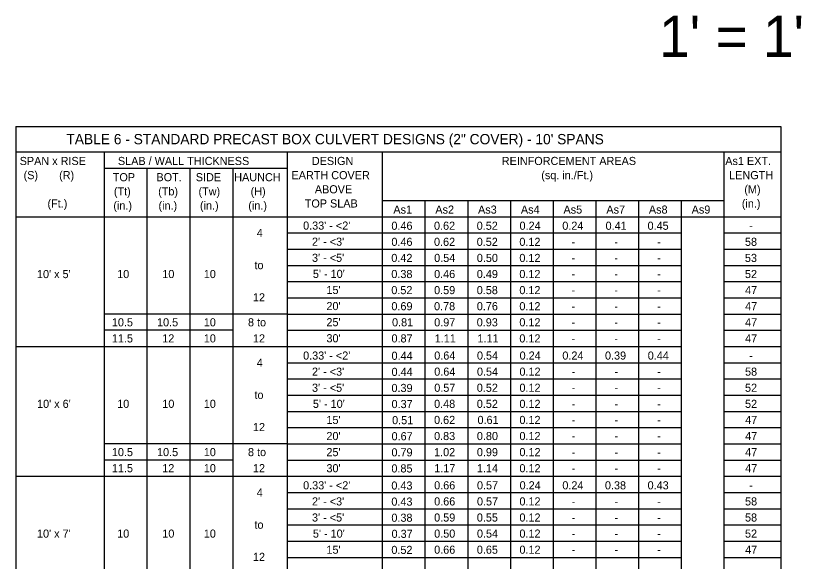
# Model space of a CAD drawing. Extents: x 10346.98 to 10349.19, y 76399.48 to 76400.59.
# Drawn here: x 10347.625 to 10348.236, y 76400.162 to 76400.586 of the extents above; entities that cross this region are included whole.
import ezdxf

# ---------------------------------------------------------------- set-up
doc = ezdxf.new("R2010")
doc.units = 0
doc.layers.add('AdhocPoint_dp', color=7, linetype='Continuous')
doc.layers.add('PlotBorder_dp', color=7, linetype='Continuous')

msp = doc.modelspace()

# ---------------------------------------------------------------- linework, layer by layer
at = {"layer": 'PlotBorder_dp'}
for p, q in [((10347.62504, 76400.49971), (10347.62504, 76399.82469)), ((10347.62504, 76400.49971), (10348.21977, 76400.49971)), ((10348.21977, 76400.49971), (10348.21977, 76399.82469)), ((10347.62504, 76400.47984), (10348.21977, 76400.47984)), ((10347.69367, 76400.47984), (10347.69367, 76399.82469)), ((10347.83612, 76400.47984), (10347.83612, 76399.82469)), ((10347.91, 76400.47984), (10347.91, 76399.82469)), ((10348.17559, 76400.47984), (10348.17559, 76399.82469)), ((10347.69367, 76400.46724), (10347.83612, 76400.46724)), ((10347.72703, 76400.46724), (10347.72703, 76399.82469)), ((10347.76039, 76400.46724), (10347.76039, 76399.82469)), ((10347.79375, 76400.46724), (10347.79375, 76399.82469)), ((10347.91, 76400.44209), (10348.17559, 76400.44209)), ((10347.9432, 76400.44209), (10347.9432, 76399.82469)), ((10347.97639, 76400.44209), (10347.97639, 76399.82469)), ((10348.00959, 76400.44209), (10348.00959, 76399.82469)), ((10348.04279, 76400.44209), (10348.04279, 76399.82469)), ((10348.07599, 76400.44209), (10348.07599, 76399.82469)), ((10348.07599, 76400.44209), (10348.07599, 76399.82469)), ((10348.10919, 76400.44209), (10348.10919, 76399.82469)), ((10348.14239, 76400.44209), (10348.14239, 76399.82469)), ((10347.62504, 76400.42949), (10348.21977, 76400.42949)), ((10347.83612, 76400.41689), (10348.14239, 76400.41689)), ((10348.17559, 76400.41689), (10348.21977, 76400.41689)), ((10347.83612, 76400.40429), (10348.14239, 76400.40429)), ((10348.17559, 76400.40429), (10348.21977, 76400.40429)), ((10347.83612, 76400.39169), (10348.14239, 76400.39169)), ((10348.17559, 76400.39169), (10348.21977, 76400.39169)), ((10347.83612, 76400.37909), (10348.14239, 76400.37909)), ((10348.17559, 76400.37909), (10348.21977, 76400.37909)), ((10347.83612, 76400.36649), (10348.14239, 76400.36649)), ((10348.17559, 76400.36649), (10348.21977, 76400.36649)), ((10347.83612, 76400.35389), (10347.69367, 76400.35389)), ((10347.83612, 76400.35389), (10348.14239, 76400.35389)), ((10348.17559, 76400.35389), (10348.21977, 76400.35389)), ((10347.79375, 76400.34129), (10347.69367, 76400.34129)), ((10347.83612, 76400.34129), (10348.14239, 76400.34129)), ((10348.17559, 76400.34129), (10348.21977, 76400.34129)), ((10347.62504, 76400.32869), (10348.14239, 76400.32869)), ((10347.83673, 76400.32869), (10347.9089, 76400.32869)), ((10348.17559, 76400.32869), (10348.21977, 76400.32869)), ((10347.83612, 76400.31609), (10348.14239, 76400.31609)), ((10348.17559, 76400.31609), (10348.21977, 76400.31609)), ((10347.83612, 76400.30349), (10348.14239, 76400.30349)), ((10348.17559, 76400.30349), (10348.21977, 76400.30349)), ((10347.83612, 76400.29089), (10348.14239, 76400.29089)), ((10348.17559, 76400.29089), (10348.21977, 76400.29089)), ((10347.83612, 76400.27829), (10348.14239, 76400.27829)), ((10348.17559, 76400.27829), (10348.21977, 76400.27829)), ((10347.83612, 76400.26569), (10348.14239, 76400.26569)), ((10348.17559, 76400.26569), (10348.21977, 76400.26569)), ((10347.83612, 76400.25309), (10347.69367, 76400.25309)), ((10347.83612, 76400.25309), (10348.14239, 76400.25309)), ((10348.17559, 76400.25309), (10348.21977, 76400.25309)), ((10347.79375, 76400.24049), (10347.69367, 76400.24049)), ((10347.83612, 76400.24049), (10348.14239, 76400.24049)), ((10347.83673, 76400.24049), (10347.9089, 76400.24049)), ((10348.17559, 76400.24049), (10348.21977, 76400.24049)), ((10347.62504, 76400.22789), (10348.14239, 76400.22789)), ((10348.17559, 76400.22789), (10348.21977, 76400.22789)), ((10347.83612, 76400.21529), (10348.14239, 76400.21529)), ((10348.17559, 76400.21529), (10348.21977, 76400.21529)), ((10347.83612, 76400.20269), (10348.14239, 76400.20269)), ((10348.17559, 76400.20269), (10348.21977, 76400.20269)), ((10347.83612, 76400.19009), (10348.14239, 76400.19009)), ((10348.17559, 76400.19009), (10348.21977, 76400.19009)), ((10347.83612, 76400.17749), (10348.14239, 76400.17749)), ((10348.17559, 76400.17749), (10348.21977, 76400.17749)), ((10347.83612, 76400.16489), (10348.14239, 76400.16489)), ((10348.17559, 76400.16489), (10348.21977, 76400.16489))]:
    msp.add_line(p, q, dxfattribs=at)

# ---------------------------------------------------------------- texts
at = {"layer": 'AdhocPoint_dp'}
for s, height, p in [("1' = 1'", 0.032, (10348.12518, 76400.55363)), ('TABLE 6 - STANDARD PRECAST BOX CULVERT DESIGNS (2" COVER) - 10\' SPANS', 0.008, (10347.66442, 76400.48578)), ('SLAB / WALL THICKNESS', 0.0063, (10347.70449, 76400.46968)), ('As1', 0.0063, (10347.91862, 76400.43192)), ('As2', 0.0063, (10347.95125, 76400.43192)), ('As3', 0.0063, (10347.98444, 76400.43192)), ('As4', 0.0063, (10348.01777, 76400.43192)), ('As5', 0.0063, (10348.05087, 76400.43192)), ('As7', 0.0063, (10348.08421, 76400.43192)), ('As8', 0.0063, (10348.11726, 76400.43192)), ('As9', 0.0063, (10348.15051, 76400.43192)), ("10' x 5'", 0.0063, (10347.64157, 76400.38182))]:
    msp.add_text(s, height=height, dxfattribs=at).set_placement(p)
at = {"layer": 'PlotBorder_dp'}
for s, p in [('SPAN x RISE', (10347.62812, 76400.46968)), ('DESIGN', (10347.85522, 76400.46968)), ('REINFORCEMENT AREAS', (10348.0029, 76400.46968)), ('(S)       (R)', (10347.63117, 76400.45868)), ('EARTH COVER', (10347.83943, 76400.45868)), ('(sq. in./Ft.)', (10348.03359, 76400.45868)), ('TOP', (10347.7005, 76400.45708)), ('BOT.', (10347.73443, 76400.45708)), ('SIDE', (10347.76502, 76400.45708)), ('HAUNCH', (10347.79491, 76400.45708)), ('(Tt)', (10347.70134, 76400.44608)), ('(Tb)', (10347.73577, 76400.44608)), ('(Tw)', (10347.76713, 76400.44608)), ('(H)', (10347.80766, 76400.44608)), ('ABOVE', (10347.85757, 76400.44768)), ('(Ft.)', (10347.64974, 76400.43668)), ('(in.)', (10347.70095, 76400.43508)), ('(in.)', (10347.73604, 76400.43508)), ('(in.)', (10347.76828, 76400.43508)), ('(in.)', (10347.80585, 76400.43508)), ('TOP SLAB', (10347.84974, 76400.43668)), ("0.33' - <2'", (10347.84847, 76400.41948)), ('0.46', (10347.91709, 76400.41937)), ('0.62', (10347.95022, 76400.41937)), ('0.52', (10347.98342, 76400.41937)), ('0.24', (10348.0167, 76400.41937)), ('0.24', (10348.04993, 76400.41937)), ('0.41', (10348.08359, 76400.41937)), ('0.45', (10348.11623, 76400.41937)), ('4', (10347.81242, 76400.41377)), ("2' - <3'", (10347.85537, 76400.40698)), ('0.46', (10347.91709, 76400.40687)), ('0.62', (10347.95022, 76400.40687)), ('0.52', (10347.98342, 76400.40687)), ('0.12', (10348.01658, 76400.40687)), ('-', (10348.05721, 76400.40687)), ('-', (10348.09042, 76400.40687)), ('-', (10348.1236, 76400.40687)), ("3' - <5'", (10347.85537, 76400.39448)), ('0.42', (10347.91702, 76400.39437)), ('0.54', (10347.95034, 76400.39437)), ('0.50', (10347.9835, 76400.39437)), ('0.12', (10348.01658, 76400.39437)), ('-', (10348.05721, 76400.39437)), ('-', (10348.09042, 76400.39437)), ('-', (10348.1236, 76400.39437)), ('to', (10347.81064, 76400.38877)), ('10', (10347.70392, 76400.38187)), ('10', (10347.73901, 76400.38187)), ('10', (10347.77125, 76400.38187)), ("5' - 10'", (10347.85608, 76400.38198)), ('0.38', (10347.91704, 76400.38187)), ('0.46', (10347.95029, 76400.38187)), ('0.49', (10347.98349, 76400.38187)), ('0.12', (10348.01658, 76400.38187)), ('-', (10348.05721, 76400.38187)), ('-', (10348.09042, 76400.38187)), ('-', (10348.1236, 76400.38187)), ("15'", (10347.8666, 76400.36948)), ('0.52', (10347.91702, 76400.36937)), ('0.59', (10347.95029, 76400.36937)), ('0.58', (10347.98344, 76400.36937)), ('0.12', (10348.01658, 76400.36937)), ('12', (10347.80947, 76400.36377)), ('-', (10348.05721, 76400.36937)), ('-', (10348.09042, 76400.36937)), ('-', (10348.1236, 76400.36937)), ("20'", (10347.8666, 76400.35698)), ('0.69', (10347.91709, 76400.35687)), ('0.78', (10347.95024, 76400.35687)), ('0.76', (10347.98349, 76400.35687)), ('0.12', (10348.01658, 76400.35687)), ('-', (10348.05721, 76400.35687)), ('-', (10348.09042, 76400.35687)), ('-', (10348.1236, 76400.35687)), ('10.5', (10347.6998, 76400.34437)), ('10.5', (10347.73489, 76400.34437)), ('10', (10347.77125, 76400.34437)), ('8 to', (10347.8056, 76400.34437)), ("25'", (10347.8666, 76400.34448)), ('0.81', (10347.91759, 76400.34437)), ('0.97', (10347.95036, 76400.34437)), ('0.93', (10347.98342, 76400.34437)), ('0.12', (10348.01658, 76400.34437)), ('-', (10348.05721, 76400.34437)), ('-', (10348.09042, 76400.34437)), ('-', (10348.1236, 76400.34437)), ('11.5', (10347.6998, 76400.33187)), ('12', (10347.73894, 76400.33187)), ('10', (10347.77125, 76400.33187)), ('12', (10347.80947, 76400.33187)), ("30'", (10347.8666, 76400.33198)), ('0.87', (10347.91716, 76400.33187)), ('1.11', (10347.95079, 76400.33187)), ('1.11', (10347.98399, 76400.33187)), ('0.12', (10348.01658, 76400.33187)), ('-', (10348.05721, 76400.33187)), ('-', (10348.09042, 76400.33187)), ('-', (10348.1236, 76400.33187)), ("0.33' - <2'", (10347.84847, 76400.31854)), ('0.44', (10347.9172, 76400.31838)), ('0.64', (10347.9504, 76400.31854)), ('0.54', (10347.9836, 76400.31854)), ('0.24', (10348.01675, 76400.31854)), ('0.24', (10348.04999, 76400.31854)), ('0.39', (10348.08314, 76400.31854)), ('0.44', (10348.11638, 76400.31854)), ('4', (10347.81242, 76400.31297)), ('-', (10348.19531, 76400.31854)), ("2' - <3'", (10347.85537, 76400.30604)), ('0.44', (10347.9172, 76400.30588)), ('0.64', (10347.9504, 76400.30604)), ('0.54', (10347.9836, 76400.30604)), ('0.12', (10348.01663, 76400.30604)), ('58', (10348.192, 76400.30604)), ('-', (10348.05726, 76400.30604)), ('-', (10348.09047, 76400.30604)), ('-', (10348.12366, 76400.30604)), ("3' - <5'", (10347.85537, 76400.29354)), ('0.39', (10347.91714, 76400.29338)), ('0.57', (10347.95041, 76400.29354)), ('0.52', (10347.98347, 76400.29354)), ('0.12', (10348.01663, 76400.29354)), ('52', (10348.19198, 76400.29354)), ('to', (10347.81064, 76400.28797)), ('-', (10348.05726, 76400.29354)), ('-', (10348.09047, 76400.29354)), ('-', (10348.12366, 76400.29354)), ("10' x 6'", (10347.64164, 76400.28104)), ('10', (10347.70392, 76400.28107)), ('10', (10347.73901, 76400.28107)), ('10', (10347.77125, 76400.28107)), ('10', (10347.77125, 76400.28107)), ("5' - 10'", (10347.85608, 76400.28104)), ('0.37', (10347.91721, 76400.28088)), ('0.48', (10347.95029, 76400.28104)), ('0.52', (10347.98347, 76400.28104)), ('0.12', (10348.01663, 76400.28104)), ('52', (10348.19198, 76400.28104)), ('-', (10348.05726, 76400.28104)), ('-', (10348.09047, 76400.28104)), ('-', (10348.12366, 76400.28104)), ('12', (10347.80947, 76400.26297)), ("15'", (10347.8666, 76400.26854)), ('0.51', (10347.91764, 76400.26838)), ('0.62', (10347.95027, 76400.26854)), ('0.61', (10347.98404, 76400.26854)), ('0.12', (10348.01663, 76400.26854)), ('-', (10348.05726, 76400.26854)), ('-', (10348.09047, 76400.26854)), ('-', (10348.12366, 76400.26854)), ('47', (10348.19212, 76400.26854)), ("20'", (10347.8666, 76400.25604)), ('0.67', (10347.91721, 76400.25588)), ('0.83', (10347.95027, 76400.25604)), ('0.80', (10347.98355, 76400.25604)), ('0.12', (10348.01663, 76400.25604)), ('-', (10348.05726, 76400.25604)), ('-', (10348.09047, 76400.25604)), ('-', (10348.12366, 76400.25604)), ('47', (10348.19212, 76400.25604)), ('10.5', (10347.6998, 76400.24357)), ('10.5', (10347.73489, 76400.24357)), ('10', (10347.77125, 76400.24357)), ('10', (10347.77125, 76400.24357)), ('8 to', (10347.8056, 76400.24357)), ("25'", (10347.8666, 76400.24354)), ('0.79', (10347.91714, 76400.24338)), ('1.02', (10347.95027, 76400.24354)), ('0.99', (10347.98354, 76400.24354)), ('0.12', (10348.01663, 76400.24354)), ('-', (10348.05726, 76400.24354)), ('-', (10348.09047, 76400.24354)), ('-', (10348.12366, 76400.24354)), ('47', (10348.19212, 76400.24354)), ('11.5', (10347.6998, 76400.23107)), ('12', (10347.73894, 76400.23107)), ('10', (10347.77125, 76400.23107)), ('10', (10347.77125, 76400.23107)), ('12', (10347.80947, 76400.23107)), ("30'", (10347.8666, 76400.23104)), ('0.85', (10347.9171, 76400.23088)), ('1.17', (10347.95041, 76400.23104)), ('1.14', (10347.9836, 76400.23104)), ('0.12', (10348.01663, 76400.23104)), ('-', (10348.05726, 76400.23104)), ('-', (10348.09047, 76400.23104)), ('-', (10348.12366, 76400.23104)), ('47', (10348.19212, 76400.23104)), ("0.33' - <2'", (10347.84847, 76400.21776)), ('0.43', (10347.91707, 76400.2176)), ('0.66', (10347.95034, 76400.21776)), ('0.57', (10347.98361, 76400.21776)), ('0.24', (10348.01675, 76400.21776)), ('0.24', (10348.04999, 76400.21776)), ('0.38', (10348.08309, 76400.21776)), ('0.43', (10348.11625, 76400.21776)), ('-', (10348.19531, 76400.21776)), ('4', (10347.81242, 76400.21217)), ("2' - <3'", (10347.85537, 76400.20526)), ('0.43', (10347.91707, 76400.2051)), ('0.66', (10347.95034, 76400.20526)), ('0.57', (10347.98361, 76400.20526)), ('0.12', (10348.01663, 76400.20526)), ('-', (10348.05726, 76400.20526)), ('-', (10348.09047, 76400.20526)), ('-', (10348.12366, 76400.20526)), ('58', (10348.192, 76400.20526)), ("3' - <5'", (10347.85537, 76400.19276)), ('0.38', (10347.91709, 76400.1926)), ('0.59', (10347.95034, 76400.19276)), ('0.55', (10347.9835, 76400.19276)), ('0.12', (10348.01663, 76400.19276)), ('58', (10348.192, 76400.19276)), ('to', (10347.81064, 76400.18717)), ('-', (10348.05726, 76400.19276)), ('-', (10348.09047, 76400.19276)), ('-', (10348.12366, 76400.19276)), ("10' x 7'", (10347.64159, 76400.18026)), ('10', (10347.70392, 76400.18027)), ('10', (10347.73901, 76400.18027)), ('10', (10347.77125, 76400.18027)), ("5' - 10'", (10347.85608, 76400.18026)), ('0.37', (10347.91721, 76400.1801)), ('0.50', (10347.95035, 76400.18026)), ('0.54', (10347.9836, 76400.18026)), ('0.12', (10348.01663, 76400.18026)), ('52', (10348.19198, 76400.18026)), ('-', (10348.05726, 76400.18026)), ('-', (10348.09047, 76400.18026)), ('-', (10348.12366, 76400.18026)), ("15'", (10347.8666, 76400.16776)), ('0.52', (10347.91707, 76400.1676)), ('0.66', (10347.95034, 76400.16776)), ('0.65', (10347.9835, 76400.16776)), ('0.12', (10348.01663, 76400.16776)), ('47', (10348.19212, 76400.16776)), ('12', (10347.80947, 76400.16217)), ('-', (10348.05726, 76400.16776)), ('-', (10348.09047, 76400.16776)), ('-', (10348.12366, 76400.16776))]:
    msp.add_text(s, height=0.0063, dxfattribs=at).set_placement(p)
for s, p in [('As1 EXT.', (10348.17663, 76400.46968)), ('LENGTH', (10348.17966, 76400.45868)), ('(M)', (10348.19146, 76400.44768)), ('(in.)', (10348.1895, 76400.43668)), ('-', (10348.19526, 76400.41937)), ('58', (10348.19195, 76400.40687)), ('53', (10348.19192, 76400.39437)), ('52', (10348.19193, 76400.38187)), ('47', (10348.19207, 76400.36937)), ('47', (10348.19207, 76400.35687)), ('47', (10348.19207, 76400.34437)), ('47', (10348.19207, 76400.33187))]:
    msp.add_text(s, height=0.0063, rotation=360, dxfattribs=at).set_placement(p)

doc.saveas('drawing.dxf')
